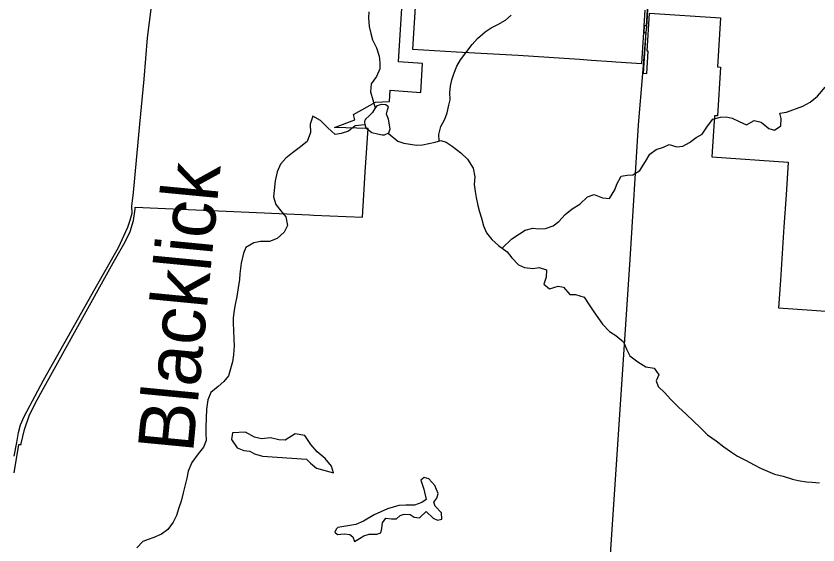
# Model space of a CAD drawing. Extents: x 0 to 91.3, y -0.7 to 22.
# Drawn here: x 3.152 to 4.519, y 16.443 to 17.345 of the extents above; entities that cross this region are included whole.
import ezdxf

# ---------------------------------------------------------------- set-up
doc = ezdxf.new("R2010")
doc.units = 0
for name, color, linetype in [('GM_X_Corporation', 7, 'Continuous'), ('GM_X_County_Road', 7, 'Continuous'), ('GM_X_Minor_Lake', 7, 'Continuous'), ('GM_X_Minor_River', 7, 'Continuous'), ('GM_X_Minor_River_Text', 7, 'Continuous')]:
    doc.layers.add(name, color=color, linetype=linetype)

msp = doc.modelspace()

# ---------------------------------------------------------------- linework, layer by layer
at = {"layer": 'GM_X_Corporation'}
for points in [[(3.1485, 16.5665), (3.1565, 16.6147), (3.1604, 16.6145), (3.1607, 16.6166), (3.1661, 16.6403), (3.1742, 16.6632), (3.1852, 16.6857), (3.1996, 16.7121), (3.3176, 16.9243), (3.3378, 16.9602), (3.3462, 16.9777), (3.3519, 16.9962), (3.3549, 17.0154), (3.3552, 17.0192), (3.6519, 17.0059), (3.659, 17.0056), (3.7424, 17.0018), (3.7448, 17.0403), (3.7472, 17.0786), (3.7519, 17.153), (3.6948, 17.155), (3.7291, 17.1681), (3.727, 17.1768), (3.7646, 17.1981), (3.7887, 17.1991), (3.7898, 17.2182), (3.842, 17.2143), (3.8447, 17.2641), (3.8037, 17.2665), (3.8193, 17.5135)], [(3.8419, 17.5135), (3.8279, 17.2882), (3.9028, 17.2837), (3.9759, 17.2798), (4.0079, 17.278), (4.1125, 17.271), (4.1325, 17.2697), (4.1673, 17.2674), (4.174, 17.2669), (4.2186, 17.2638), (4.2203, 17.2903), (4.2219, 17.3166), (4.2219, 17.3166), (4.2227, 17.3281), (4.2227, 17.3281), (4.2244, 17.3548)], [(4.2353, 17.48), (4.2258, 17.3279), (4.2227, 17.3281), (4.2219, 17.3166), (4.2251, 17.3165), (4.2207, 17.2471), (4.2251, 17.2472), (4.227, 17.2471), (4.2293, 17.2849), (4.2275, 17.285), (4.2317, 17.3498), (4.3527, 17.3419), (4.3475, 17.2581), (4.3524, 17.2578), (4.3473, 17.1745), (4.3423, 17.1748), (4.3376, 17.1049), (4.4681, 17.096), (4.4644, 17.04), (4.4608, 16.9857), (4.4547, 16.8944), (4.4516, 16.8473), (4.573, 16.8392)]]:
    msp.add_lwpolyline(points, dxfattribs=at)
at = {"layer": 'GM_X_County_Road'}
for p, q in [((4.2261, 17.317), (4.2269, 17.3269)), ((4.2202, 17.2471), (4.2261, 17.317))]:
    msp.add_line(p, q, dxfattribs=at)
for points in [[(4.2269, 17.3269), (4.2276, 17.3349), (4.235, 17.4759)], [(3.1485, 16.595), (3.1531, 16.6183), (3.1561, 16.6348), (3.1593, 16.6479), (3.1658, 16.6626), (3.1989, 16.7243), (3.2865, 16.8802), (3.3263, 16.9506), (3.3424, 16.985), (3.3462, 16.997), (3.3499, 17.0091), (3.3492, 17.0206), (3.352, 17.0443), (3.3628, 17.1604), (3.3701, 17.2374), (3.3762, 17.3079), (3.3826, 17.361)], [(4.112, 15.5855), (4.1196, 15.6918), (4.1232, 15.7838), (4.1286, 15.9666), (4.1509, 16.2143), (4.1988, 16.9297), (4.2129, 17.1593), (4.2202, 17.2471)]]:
    msp.add_lwpolyline(points, dxfattribs=at)
at = {"layer": 'GM_X_Minor_Lake'}
for points in [[(3.7483, 17.1545), (3.7581, 17.1464), (3.768, 17.1441), (3.776, 17.1425), (3.7801, 17.1421), (3.7874, 17.1459), (3.7893, 17.1527), (3.7867, 17.169), (3.7834, 17.1774), (3.7853, 17.185), (3.7865, 17.1899), (3.782, 17.1937), (3.7748, 17.1938), (3.7668, 17.1916), (3.7633, 17.1874), (3.7595, 17.1802), (3.753, 17.1742)], [(3.753, 17.1742), (3.7482, 17.1694), (3.7465, 17.1672), (3.7459, 17.1648), (3.7459, 17.163), (3.7463, 17.1605), (3.7483, 17.1545)], [(3.6469, 16.5899), (3.6537, 16.5827), (3.6642, 16.5743), (3.693, 16.5665), (3.6897, 16.5775), (3.6788, 16.5905), (3.6652, 16.602), (3.6542, 16.6145), (3.6441, 16.6298), (3.6278, 16.6329), (3.6106, 16.622), (3.6, 16.6225), (3.5856, 16.626), (3.5704, 16.6245), (3.5583, 16.6269), (3.5428, 16.6357), (3.5208, 16.6347), (3.5192, 16.6233), (3.5286, 16.6092), (3.5403, 16.6042), (3.5502, 16.603), (3.5581, 16.5988), (3.5721, 16.5949)], [(3.5721, 16.5949), (3.6469, 16.5899)], [(3.7004, 16.4731), (3.6977, 16.4701), (3.6954, 16.4651), (3.6996, 16.4613), (3.7114, 16.4624), (3.7208, 16.4612), (3.7257, 16.4574), (3.7287, 16.4494), (3.7375, 16.4543), (3.7447, 16.4588), (3.7535, 16.4617), (3.7588, 16.4617), (3.7668, 16.4617), (3.7736, 16.4643), (3.7756, 16.4715), (3.7764, 16.4814), (3.7821, 16.4893), (3.7916, 16.4877), (3.8003, 16.4877), (3.8068, 16.4937), (3.8133, 16.4959), (3.8235, 16.4955), (3.8307, 16.4909), (3.8398, 16.4897), (3.8509, 16.5003), (3.863, 16.4892), (3.8701, 16.4857), (3.8774, 16.4872), (3.8771, 16.4982), (3.8665, 16.5093), (3.8639, 16.5165), (3.8692, 16.5229), (3.8712, 16.5313), (3.8656, 16.5446), (3.8554, 16.556), (3.8478, 16.5584), (3.8421, 16.5538), (3.8469, 16.5386), (3.851, 16.5208), (3.8438, 16.5155), (3.8308, 16.5114), (3.8164, 16.5111), (3.8046, 16.5104), (3.7853, 16.5052), (3.7624, 16.4947), (3.7441, 16.4838), (3.7308, 16.4782)], [(3.7308, 16.4782), (3.7004, 16.4731)]]:
    msp.add_lwpolyline(points, dxfattribs=at)
at = {"layer": 'GM_X_Minor_River'}
for points in [[(3.753, 17.3518), (3.7525, 17.3419), (3.7536, 17.3271), (3.7569, 17.315), (3.7595, 17.3043), (3.7662, 17.2906), (3.7711, 17.2765), (3.7718, 17.2648), (3.7717, 17.2549), (3.7663, 17.2417), (3.7571, 17.2292)], [(3.8729, 17.1317), (3.8727, 17.1427), (3.8762, 17.1564), (3.8828, 17.1689), (3.8866, 17.1798), (3.8897, 17.1927), (3.8921, 17.2022), (3.8914, 17.2144), (3.8926, 17.2254), (3.8949, 17.236), (3.898, 17.2462), (3.9034, 17.2591), (3.9092, 17.2704), (3.9184, 17.2821), (3.9295, 17.2961), (3.9387, 17.3063), (3.9516, 17.318), (3.9619, 17.3244), (3.9733, 17.3304), (3.9859, 17.3379), (3.9958, 17.3462)], [(3.7571, 17.2292), (3.7559, 17.2155), (3.7642, 17.1885)], [(3.9806, 16.9491), (3.9969, 16.9651), (4.0098, 16.9738), (4.0194, 16.9798), (4.033, 16.9831), (4.0425, 16.9823), (4.0543, 16.9826), (4.0672, 16.9871), (4.0771, 16.9946), (4.0878, 17.0063), (4.0997, 17.0165), (4.113, 17.024), (4.126, 17.0365), (4.137, 17.0406), (4.1514, 17.0348), (4.1635, 17.034), (4.1723, 17.0484), (4.1758, 17.0582), (4.1835, 17.0718), (4.1934, 17.0737), (4.2029, 17.074), (4.2151, 17.0815), (4.2246, 17.0966), (4.2323, 17.1091), (4.243, 17.1174), (4.2555, 17.1215), (4.2651, 17.1256), (4.2779, 17.1221), (4.2886, 17.1232), (4.3, 17.1292), (4.3111, 17.1379), (4.3213, 17.1435), (4.3305, 17.1571), (4.3393, 17.1688), (4.3526, 17.1725), (4.3621, 17.1729), (4.3724, 17.1709), (4.3845, 17.1651), (4.397, 17.1594), (4.4099, 17.1665), (4.4217, 17.1638), (4.4349, 17.1534), (4.4447, 17.15), (4.4554, 17.1575), (4.4559, 17.17), (4.454, 17.1795), (4.465, 17.181), (4.4932, 17.1914), (4.5054, 17.1982), (4.518, 17.2084), (4.531, 17.2235)], [(3.7466, 17.1594), (3.7301, 17.1576), (3.7187, 17.1486), (3.7058, 17.1445), (3.6959, 17.143), (3.6834, 17.1541), (3.671, 17.1667), (3.6577, 17.174), (3.6531, 17.1604), (3.6538, 17.1463), (3.648, 17.1308), (3.6346, 17.1199), (3.6232, 17.1119), (3.6117, 17.1025), (3.6026, 17.0923), (3.5968, 17.0795), (3.5933, 17.0639), (3.592, 17.0476), (3.5908, 17.0366), (3.5946, 17.0237), (3.6032, 17.013), (3.6115, 17.0027), (3.6148, 16.9879), (3.6087, 16.9762), (3.5972, 16.9656), (3.5839, 16.9607), (3.5687, 16.9605), (3.557, 16.9582), (3.5436, 16.9504), (3.5394, 16.9405), (3.5355, 16.9238), (3.5335, 16.9056), (3.533, 16.8958), (3.5307, 16.8817), (3.5283, 16.8666), (3.5252, 16.8533), (3.5236, 16.8438), (3.522, 16.8302), (3.5219, 16.8203), (3.5223, 16.81), (3.5229, 16.793), (3.5236, 16.7835), (3.5227, 16.7675), (3.5208, 16.7554), (3.5173, 16.7433), (3.5138, 16.7319), (3.5061, 16.7217), (3.4966, 16.7134), (3.484, 16.7032), (3.479, 16.6907), (3.4766, 16.6748), (3.4758, 16.6596), (3.4753, 16.6441), (3.4756, 16.6342), (3.4759, 16.6213), (3.4717, 16.6103), (3.4625, 16.5986), (3.4514, 16.5842), (3.4452, 16.5691), (3.4429, 16.557), (3.4401, 16.546), (3.437, 16.532), (3.4331, 16.5179), (3.4289, 16.5051), (3.4254, 16.4937), (3.4196, 16.4823), (3.4104, 16.4695), (3.4001, 16.462), (3.3868, 16.456), (3.3773, 16.4526), (3.3678, 16.4496), (3.3579, 16.4387)], [(3.7859, 17.1451), (3.8028, 17.1314), (3.8127, 17.1283), (3.8237, 17.1263), (3.8347, 17.1247), (3.8445, 17.1251), (3.8556, 17.1273), (3.8662, 17.1299), (3.8757, 17.1325), (3.8852, 17.1301), (3.8954, 17.1232), (3.9101, 17.1114), (3.9214, 17.1007), (3.9312, 17.0858), (3.9338, 17.0706), (3.9325, 17.0577), (3.9344, 17.0456), (3.9362, 17.0357), (3.9392, 17.022), (3.9417, 17.011), (3.9455, 17.0004), (3.9488, 16.9874), (3.954, 16.9756), (3.9631, 16.9638), (3.974, 16.9539), (3.9888, 16.9432), (3.997, 16.9329), (4.0084, 16.921), (4.0186, 16.9164), (4.033, 16.9144), (4.0436, 16.9163), (4.0561, 16.912), (4.0553, 16.8999), (4.0514, 16.8881), (4.0612, 16.8801), (4.0757, 16.8846), (4.0852, 16.883), (4.0957, 16.8704), (4.1052, 16.87), (4.12, 16.8657), (4.129, 16.8524), (4.1358, 16.8425), (4.1448, 16.8295), (4.1516, 16.8196), (4.1636, 16.8074), (4.1742, 16.8001), (4.187, 16.7894), (4.1927, 16.7757), (4.1983, 16.7658), (4.2115, 16.7555), (4.2255, 16.747), (4.2395, 16.7447), (4.2474, 16.7336), (4.2428, 16.723), (4.2465, 16.7135), (4.2575, 16.7024), (4.2673, 16.6918), (4.2809, 16.6784), (4.2941, 16.6662), (4.3069, 16.6539), (4.3171, 16.6444), (4.3307, 16.631), (4.345, 16.6207), (4.3582, 16.6107), (4.3711, 16.6016), (4.3817, 16.595), (4.3953, 16.5878), (4.4097, 16.5797), (4.4206, 16.5743), (4.4445, 16.5639), (4.4596, 16.5604), (4.4752, 16.5554), (4.485, 16.5531), (4.4994, 16.5511), (4.5089, 16.5503), (4.5211, 16.5494)]]:
    msp.add_lwpolyline(points, dxfattribs=at)

# ---------------------------------------------------------------- texts
at = {"layer": 'GM_X_Minor_River_Text'}
msp.add_text('Blacklick', height=0.09471, rotation=84.4805, dxfattribs=at).set_placement((3.4534, 16.599))

doc.saveas('drawing.dxf')
